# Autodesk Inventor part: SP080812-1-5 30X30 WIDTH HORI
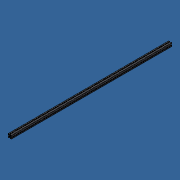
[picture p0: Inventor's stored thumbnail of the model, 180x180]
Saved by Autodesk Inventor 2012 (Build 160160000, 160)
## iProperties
Created: 2012-08
Part Number: SP080812-1-5 30X30 WIDTH HORI
Material: Aluminum-6061
Description: PROFILE 30X30
Document SubType Name: Modeling
Designer: Administrator
Stock Number: 20.1068 PROFILE 30X30
Density: 2.71 g/cm^3
FINISH: CLEAR ANODIZED
Author: Administrator
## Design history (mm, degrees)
sketch "Sketch1"
  geometry: L1 (13.5, -7.8)-(9.3, -7.8) reference; L2 (14, -12.5)-(14, -8.3) reference; L3 (8.3, -14)-(12.5, -14) reference; L4 (7.8, -9.3)-(7.8, -13.5) reference; L5 (-9.3, -7.8)-(-13.5, -7.8) reference; L6 (-7.8, -13.5)-(-7.8, -9.3) reference; L7 (-12.5, -14)-(-8.3, -14) reference; L8 (-14, -8.3)-(-14, -12.5) reference; L9 (3.286, 3.879)-(2.243, 3.657) reference; L10 (3.657, 2.243)-(3.879, 3.286) reference; L11 (3.263, 1.849)-(3.657, 2.243) reference; L12 (3.657, -2.243)-(3.263, -1.849) reference; L13 (3.879, -3.286)-(3.657, -2.243) reference; L14 (2.243, -3.657)-(3.286, -3.879) reference; L15 (1.849, -3.263)-(2.243, -3.657) reference; L16 (-2.243, -3.657)-(-1.849, -3.263) reference; L17 (-3.286, -3.879)-(-2.243, -3.657) reference; L18 (-3.657, -2.243)-(-3.879, -3.286) reference; L19 (-3.263, -1.849)-(-3.657, -2.243) reference; L20 (-3.657, 2.243)-(-3.263, 1.849) reference; L21 (-3.879, 3.286)-(-3.657, 2.243) reference; L22 (-2.243, 3.657)-(-3.286, 3.879) reference; L23 (-1.849, 3.263)-(-2.243, 3.657) reference; L24 (2.243, 3.657)-(1.849, 3.263) reference; L25 (9.3, 7.8)-(13.5, 7.8) reference; L26 (7.8, 13.5)-(7.8, 9.3) reference; L27 (12.5, 14)-(8.3, 14) reference; L28 (14, 8.3)-(14, 12.5) reference; L29 (-8.3, 14)-(-12.5, 14) reference; L30 (-7.8, 9.3)-(-7.8, 13.5) reference; L31 (-13.5, 7.8)-(-9.3, 7.8) reference; L32 (-14, 12.5)-(-14, 8.3) reference; L33 (12.5, 4.1)-(12.5, 6.8) reference; L34 (15, 4.1)-(12.5, 4.1) reference; L35 (15, 15)-(15, 4.1) reference; L36 (4.1, 15)-(15, 15) reference; L37 (4.1, 12.5)-(4.1, 15) reference; L38 (6.8, 12.5)-(4.1, 12.5) reference; L39 (6.8, 7.861)-(6.8, 12.5) reference; L40 (4.639, 5.7)-(6.8, 7.861) reference; L41 (1.497, 5.032)-(4.639, 5.7) reference; L42 (-1.497, 5.032)-(1.497, 5.032) reference; L43 (-4.639, 5.7)-(-1.497, 5.032) reference; L44 (-6.8, 7.861)-(-4.639, 5.7) reference; L45 (-6.8, 12.5)-(-6.8, 7.861) reference; L46 (-4.1, 12.5)-(-6.8, 12.5) reference; L47 (-4.1, 15)-(-4.1, 12.5) reference; L48 (-15, 15)-(-4.1, 15) reference; L49 (-15, 4.1)-(-15, 15) reference; L50 (-12.5, 4.1)-(-15, 4.1) reference; L51 (-12.5, 6.8)-(-12.5, 4.1) reference; L52 (-7.861, 6.8)-(-12.5, 6.8) reference; L53 (-5.7, 4.639)-(-7.861, 6.8) reference; L54 (-5.032, 1.497)-(-5.7, 4.639) reference; L55 (-5.032, -1.497)-(-5.032, 1.497) reference; L56 (-5.7, -4.639)-(-5.032, -1.497) reference; L57 (-7.861, -6.8)-(-5.7, -4.639) reference; L58 (-12.5, -6.8)-(-7.861, -6.8) reference; L59 (-12.5, -4.1)-(-12.5, -6.8) reference; L60 (-15, -4.1)-(-12.5, -4.1) reference; L61 (-15, -15)-(-15, -4.1) reference; L62 (-4.1, -15)-(-15, -15) reference; L63 (-4.1, -12.5)-(-4.1, -15) reference; L64 (-6.8, -12.5)-(-4.1, -12.5) reference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; A1 r 1.5 centre (9.3, -9.3) between (9.3, -7.8) and (7.8, -9.3) reference; A2 r 0.5 centre (13.5, -8.3) between (14, -8.3) and (13.5, -7.8) reference; A3 r 1.5 centre (12.5, -12.5) between (12.5, -14) and (14, -12.5) reference; A4 r 0.5 centre (8.3, -13.5) between (7.8, -13.5) and (8.3, -14) reference; A5 r 0.5 centre (-13.5, -8.3) between (-13.5, -7.8) and (-14, -8.3) reference; A6 r 1.5 centre (-9.3, -9.3) between (-7.8, -9.3) and (-9.3, -7.8) reference; A7 r 0.5 centre (-8.3, -13.5) between (-8.3, -14) and (-7.8, -13.5) reference; A8 r 1.5 centre (-12.5, -12.5) between (-14, -12.5) and (-12.5, -14) reference; A9 r 0.5 centre (3.39, 3.39) between (3.879, 3.286) and (3.286, 3.879) reference; A10 r 0.5 centre (3.39, -3.39) between (3.286, -3.879) and (3.879, -3.286) reference; A11 r 3.75 centre (0, 0) between (-1.849, -3.263) and (1.66, -3.362) reference; A12 r 0.5 centre (-3.39, -3.39) between (-3.879, -3.286) and (-3.286, -3.879) reference; A13 r 3.75 centre (0, 0) between (-3.362, 1.66) and (-3.263, -1.849) reference; A14 r 0.5 centre (-3.39, 3.39) between (-3.286, 3.879) and (-3.879, 3.286) reference; A15 r 0.5 centre (13.5, 8.3) between (13.5, 7.8) and (14, 8.3) reference; A16 r 1.5 centre (9.3, 9.3) between (7.8, 9.3) and (9.3, 7.8) reference; A17 r 0.5 centre (8.3, 13.5) between (8.3, 14) and (7.8, 13.5) reference; A18 r 1.5 centre (12.5, 12.5) between (14, 12.5) and (12.5, 14) reference; A19 r 1.5 centre (-12.5, 12.5) between (-12.5, 14) and (-14, 12.5) reference; A20 r 0.5 centre (-8.3, 13.5) between (-7.8, 13.5) and (-8.3, 14) reference; A21 r 1.5 centre (-9.3, 9.3) between (-9.3, 7.8) and (-7.8, 9.3) reference; A22 r 0.5 centre (-13.5, 8.3) between (-14, 8.3) and (-13.5, 7.8) reference; A23 r 3.75 centre (0, 0) between (-3.263, 1.849) and (-3.362, 1.66) reference; A24 r 3.75 centre (0, 0) between (3.362, 1.66) and (3.263, 1.849) reference; A25 r 3.75 centre (0, 0) between (1.849, 3.263) and (-1.849, 3.263) reference; A26 r 3.75 centre (0, 0) between (1.66, -3.362) and (1.849, -3.263) reference; A27 r 3.75 centre (0, 0) between (3.263, -1.849) and (3.362, 1.66) reference; 2 further points
  constraints: 168 end point, 54 point on circle, 27 centre point, 26 horizontal, 26 vertical, 195 other
extrude "Extrusion1" new body sketch "Sketch1" distance "d2" = 1464; taper "d3" = 0 deg
body "Solid1"
